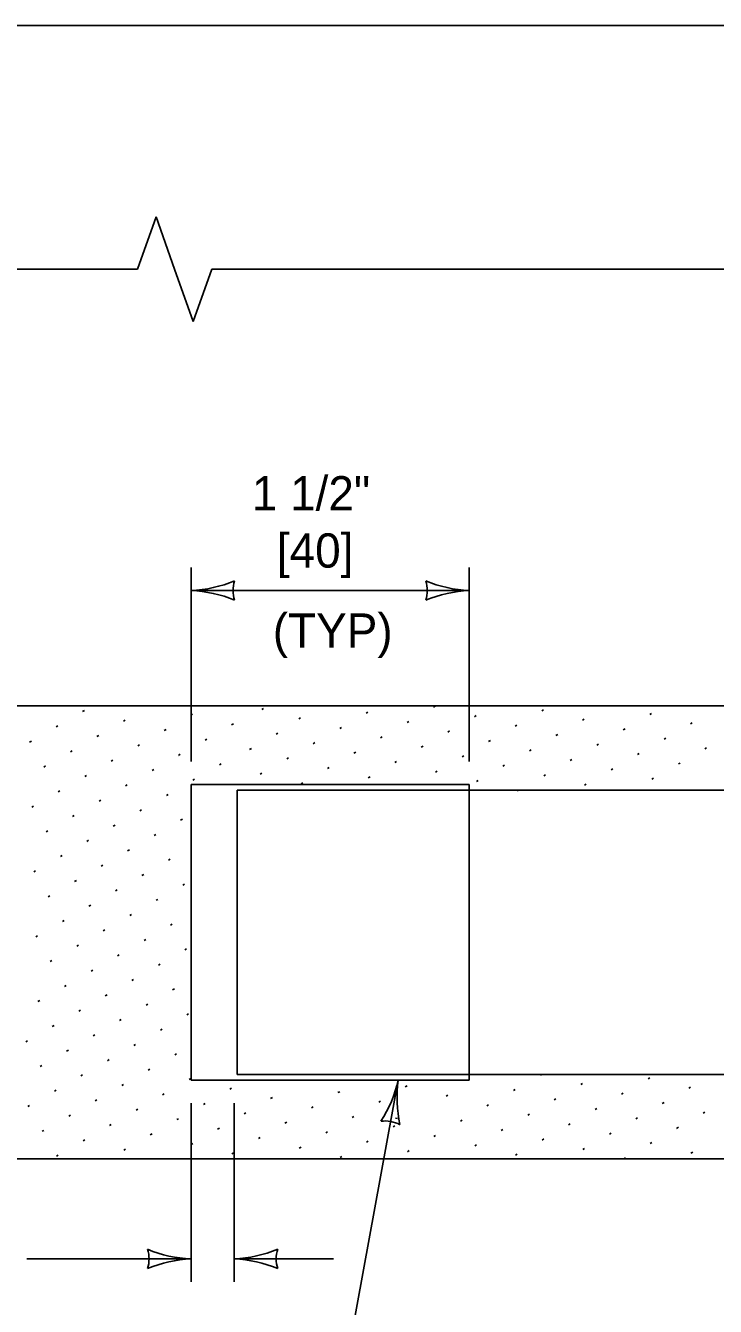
# Model space of a CAD drawing. Extents: x 49991.4 to 50021, y 49987.6 to 50011.4.
# Drawn here: x 50004.674 to 50005.88, y 49996.76 to 49998.999 of the extents above; entities that cross this region are included whole.
import ezdxf

# ---------------------------------------------------------------- set-up
doc = ezdxf.new("R2010")
doc.units = 0
for name, color, linetype in [('Level 1', 7, 'Continuous'), ('Level 2', 7, 'Continuous'), ('Level 3', 7, 'Continuous'), ('Level 4', 7, 'Continuous'), ('Level 6', 7, 'Continuous')]:
    doc.layers.add(name, color=color, linetype=linetype)

msp = doc.modelspace()

# ---------------------------------------------------------------- linework, layer by layer
at = {"layer": 'Level 1'}
for p, q in [((50002.4589, 49997.8102), (50013.6129, 49997.8102)), ((50004.963, 49997.1559), (50004.963, 49997.6726)), ((50005.4493, 49997.6726), (50004.963, 49997.6726)), ((50005.4493, 49997.1559), (50005.4493, 49997.6726)), ((50005.4493, 49997.6626), (50008.0071, 49997.6626)), ((50004.963, 49997.1659), (50004.963, 49997.1659)), ((50008.0071, 49997.1659), (50005.4493, 49997.1659)), ((50005.4493, 49997.1559), (50004.963, 49997.1559)), ((50013.6129, 49997.0183), (50002.4589, 49997.0183))]:
    msp.add_line(p, q, dxfattribs=at)
msp.add_lwpolyline([(49999.3835, 49998.9992), (50016.7501, 49998.9992), (50016.7501, 49987.7988), (49999.3835, 49987.7988)], close=True, dxfattribs=at)
at = {"layer": 'Level 3'}
for p, q in [((50004.963, 49997.7126), (50004.963, 49998.0517)), ((50005.4493, 49997.7126), (50005.4493, 49998.0517)), ((50004.963, 49998.0117), (50005.4493, 49998.0117)), ((50004.7735, 49997.8), (50004.7765, 49997.8018)), ((50004.9625, 49997.7937), (50004.9655, 49997.7954)), ((50005.0868, 49997.8039), (50005.0898, 49997.8056)), ((50005.2692, 49997.7975), (50005.2722, 49997.7993)), ((50005.3868, 49997.8078), (50005.3899, 49997.8095)), ((50005.4582, 49997.7912), (50005.4612, 49997.793)), ((50005.5759, 49997.8014), (50005.5789, 49997.8032)), ((50005.7649, 49997.7951), (50005.7679, 49997.7968)), ((50004.7271, 49997.7733), (50004.7302, 49997.775)), ((50004.8448, 49997.7835), (50004.8478, 49997.7852)), ((50005.0338, 49997.7771), (50005.0369, 49997.7789)), ((50005.1515, 49997.7873), (50005.1545, 49997.7891)), ((50005.2228, 49997.7708), (50005.2259, 49997.7725)), ((50005.3405, 49997.781), (50005.3435, 49997.7827)), ((50005.5295, 49997.7747), (50005.5326, 49997.7764)), ((50005.6472, 49997.7849), (50005.6502, 49997.7866)), ((50005.7185, 49997.7683), (50005.7216, 49997.7701)), ((50005.8362, 49997.7785), (50005.8392, 49997.7803)), ((50004.6808, 49997.7465), (50004.6838, 49997.7483)), ((50004.7985, 49997.7567), (50004.8015, 49997.7585)), ((50004.9161, 49997.7669), (50004.9192, 49997.7687)), ((50004.9875, 49997.7504), (50004.9905, 49997.7521)), ((50005.1118, 49997.7606), (50005.1148, 49997.7623)), ((50005.2942, 49997.7542), (50005.2972, 49997.756)), ((50005.4118, 49997.7644), (50005.4149, 49997.7662)), ((50005.4832, 49997.7479), (50005.4862, 49997.7497)), ((50005.6009, 49997.7581), (50005.6039, 49997.7599)), ((50005.7899, 49997.7518), (50005.7929, 49997.7535)), ((50004.7521, 49997.73), (50004.7552, 49997.7317)), ((50004.8698, 49997.7402), (50004.8728, 49997.7419)), ((50004.9411, 49997.7236), (50004.9442, 49997.7254)), ((50005.0654, 49997.7338), (50005.0685, 49997.7356)), ((50005.1765, 49997.744), (50005.1795, 49997.7458)), ((50005.2478, 49997.7275), (50005.2509, 49997.7292)), ((50005.3655, 49997.7377), (50005.3685, 49997.7394)), ((50005.5545, 49997.7314), (50005.5576, 49997.7331)), ((50005.6722, 49997.7416), (50005.6752, 49997.7433)), ((50005.7435, 49997.725), (50005.7466, 49997.7268)), ((50005.8612, 49997.7352), (50005.8642, 49997.737)), ((50004.7058, 49997.7032), (50004.7088, 49997.705)), ((50004.8235, 49997.7134), (50004.8265, 49997.7152)), ((50005.0125, 49997.7071), (50005.0155, 49997.7088)), ((50005.1302, 49997.7173), (50005.1332, 49997.719)), ((50005.3192, 49997.7109), (50005.3222, 49997.7127)), ((50005.4368, 49997.7211), (50005.4399, 49997.7229)), ((50005.5082, 49997.7046), (50005.5112, 49997.7064)), ((50005.6259, 49997.7148), (50005.6289, 49997.7166)), ((50005.8149, 49997.7085), (50005.8179, 49997.7102)), ((50004.7771, 49997.6867), (50004.7802, 49997.6884)), ((50004.8948, 49997.6969), (50004.8978, 49997.6986)), ((50004.9661, 49997.6803), (50004.9692, 49997.6821)), ((50005.0838, 49997.6905), (50005.0869, 49997.6923)), ((50005.2015, 49997.7007), (50005.2045, 49997.7025)), ((50005.2728, 49997.6842), (50005.2759, 49997.6859)), ((50005.3905, 49997.6944), (50005.3935, 49997.6961)), ((50005.5795, 49997.6881), (50005.5826, 49997.6898)), ((50005.6972, 49997.6983), (50005.7002, 49997.7)), ((50005.7685, 49997.6817), (50005.7716, 49997.6835)), ((50004.7308, 49997.6599), (50004.7338, 49997.6617)), ((50004.8485, 49997.6701), (50004.8515, 49997.6719)), ((50005.1552, 49997.674), (50005.1582, 49997.6757)), ((50005.4618, 49997.6778), (50005.4649, 49997.6796)), ((50005.5332, 49997.6613), (50005.5362, 49997.663)), ((50005.6509, 49997.6715), (50005.6539, 49997.6733)), ((50004.8021, 49997.6434), (50004.8052, 49997.6451)), ((50004.9198, 49997.6536), (50004.9228, 49997.6553)), ((50004.6845, 49997.6332), (50004.6875, 49997.6349)), ((50004.7558, 49997.6166), (50004.7588, 49997.6184)), ((50004.8735, 49997.6268), (50004.8765, 49997.6286)), ((50004.7095, 49997.5899), (50004.7125, 49997.5916)), ((50004.8271, 49997.6001), (50004.8302, 49997.6018)), ((50004.9448, 49997.6103), (50004.9478, 49997.612)), ((50004.7808, 49997.5733), (50004.7838, 49997.5751)), ((50004.8985, 49997.5835), (50004.9015, 49997.5853)), ((50004.7345, 49997.5466), (50004.7375, 49997.5483)), ((50004.8521, 49997.5568), (50004.8552, 49997.5585)), ((50004.8058, 49997.53), (50004.8088, 49997.5318)), ((50004.9235, 49997.5402), (50004.9265, 49997.542)), ((50004.6881, 49997.5198), (50004.6911, 49997.5216)), ((50004.7595, 49997.5033), (50004.7625, 49997.505)), ((50004.8771, 49997.5135), (50004.8802, 49997.5152)), ((50004.8308, 49997.4867), (50004.8338, 49997.4885)), ((50004.9485, 49997.4969), (50004.9515, 49997.4987)), ((50004.7131, 49997.4765), (50004.7161, 49997.4783)), ((50004.7845, 49997.46), (50004.7875, 49997.4617)), ((50004.9021, 49997.4702), (50004.9052, 49997.4719)), ((50004.7381, 49997.4332), (50004.7411, 49997.435)), ((50004.8558, 49997.4434), (50004.8588, 49997.4452)), ((50004.8095, 49997.4167), (50004.8125, 49997.4184)), ((50004.9271, 49997.4269), (50004.9302, 49997.4286)), ((50004.6918, 49997.4064), (50004.6948, 49997.4082)), ((50004.7631, 49997.3899), (50004.7661, 49997.3917)), ((50004.8808, 49997.4001), (50004.8838, 49997.4019)), ((50004.8345, 49997.3734), (50004.8375, 49997.3751)), ((50004.9521, 49997.3836), (50004.9552, 49997.3853)), ((50004.7168, 49997.3631), (50004.7198, 49997.3649)), ((50004.7881, 49997.3466), (50004.7911, 49997.3483)), ((50004.9058, 49997.3568), (50004.9088, 49997.3586)), ((50004.8595, 49997.3301), (50004.8625, 49997.3318)), ((50004.7418, 49997.3198), (50004.7448, 49997.3216)), ((50004.8131, 49997.3033), (50004.8161, 49997.305)), ((50004.9308, 49997.3135), (50004.9338, 49997.3153)), ((50004.6954, 49997.2931), (50004.6985, 49997.2948)), ((50004.7668, 49997.2765), (50004.7698, 49997.2783)), ((50004.8845, 49997.2868), (50004.8875, 49997.2885)), ((50004.8381, 49997.26), (50004.8411, 49997.2617)), ((50004.9558, 49997.2702), (50004.9588, 49997.272)), ((50004.7204, 49997.2498), (50004.7235, 49997.2515)), ((50004.7918, 49997.2332), (50004.7948, 49997.235)), ((50004.9095, 49997.2434), (50004.9125, 49997.2452)), ((50004.6741, 49997.223), (50004.6771, 49997.2248)), ((50004.8631, 49997.2167), (50004.8661, 49997.2184)), ((50004.7454, 49997.2065), (50004.7485, 49997.2082)), ((50004.8168, 49997.1899), (50004.8198, 49997.1917)), ((50004.9345, 49997.2001), (50004.9375, 49997.2019)), ((50004.6991, 49997.1797), (50004.7021, 49997.1815)), ((50004.8881, 49997.1734), (50004.8911, 49997.1751)), ((50005.5737, 49997.1646), (50005.5759, 49997.1659)), ((50004.7704, 49997.1632), (50004.7735, 49997.1649)), ((50004.8418, 49997.1466), (50004.8448, 49997.1484)), ((50004.9595, 49997.1568), (50004.9625, 49997.1586)), ((50005.2052, 49996.4992), (50005.3252, 49997.1559)), ((50005.3375, 49997.1442), (50005.3405, 49997.1459)), ((50005.6442, 49997.148), (50005.6472, 49997.1498)), ((50005.7618, 49997.1582), (50005.7649, 49997.16)), ((50005.8332, 49997.1417), (50005.8362, 49997.1434)), ((50004.7241, 49997.1364), (50004.7271, 49997.1382)), ((50004.7954, 49997.1199), (50004.7985, 49997.1216)), ((50004.9131, 49997.1301), (50004.9161, 49997.1318)), ((50005.0308, 49997.1403), (50005.0338, 49997.142)), ((50005.1021, 49997.1238), (50005.1052, 49997.1255)), ((50005.2198, 49997.134), (50005.2228, 49997.1357)), ((50005.4088, 49997.1276), (50005.4118, 49997.1294)), ((50005.5265, 49997.1378), (50005.5295, 49997.1396)), ((50005.5978, 49997.1213), (50005.6009, 49997.123)), ((50005.7155, 49997.1315), (50005.7185, 49997.1332)), ((50004.6778, 49997.1097), (50004.6808, 49997.1114)), ((50004.8668, 49997.1033), (50004.8698, 49997.1051)), ((50004.963, 49996.8034), (50004.963, 49997.1159)), ((50004.9845, 49997.1135), (50004.9875, 49997.1153)), ((50005.0384, 49996.8034), (50005.0384, 49997.1159)), ((50005.0558, 49997.097), (50005.0588, 49997.0987)), ((50005.1735, 49997.1072), (50005.1765, 49997.109)), ((50005.2911, 49997.1174), (50005.2942, 49997.1192)), ((50005.4802, 49997.1111), (50005.4832, 49997.1128)), ((50005.6692, 49997.1047), (50005.6722, 49997.1065)), ((50005.7868, 49997.1149), (50005.7899, 49997.1167)), ((50005.8582, 49997.0984), (50005.8612, 49997.1001)), ((50004.7491, 49997.0931), (50004.7521, 49997.0949)), ((50004.8204, 49997.0766), (50004.8235, 49997.0783)), ((50004.9381, 49997.0868), (50004.9411, 49997.0885)), ((50005.1271, 49997.0804), (50005.1302, 49997.0822)), ((50005.2448, 49997.0907), (50005.2478, 49997.0924)), ((50005.3202, 49997.0896), (50005.3237, 49997.0891)), ((50005.4338, 49997.0843), (50005.4368, 49997.0861)), ((50005.5515, 49997.0945), (50005.5545, 49997.0963)), ((50005.6228, 49997.078), (50005.6259, 49997.0797)), ((50005.7405, 49997.0882), (50005.7435, 49997.0899)), ((50004.7028, 49997.0664), (50004.7058, 49997.0681)), ((50004.8918, 49997.06), (50004.8948, 49997.0618)), ((50005.0095, 49997.0702), (50005.0125, 49997.072)), ((50005.0808, 49997.0537), (50005.0838, 49997.0554)), ((50005.1985, 49997.0639), (50005.2015, 49997.0657)), ((50005.3161, 49997.0741), (50005.3192, 49997.0759)), ((50005.3875, 49997.0576), (50005.3905, 49997.0593)), ((50005.5052, 49997.0678), (50005.5082, 49997.0695)), ((50005.6942, 49997.0614), (50005.6972, 49997.0632)), ((50005.8118, 49997.0716), (50005.8149, 49997.0734)), ((50004.7741, 49997.0498), (50004.7771, 49997.0516)), ((50004.8454, 49997.0333), (50004.8485, 49997.035)), ((50004.9631, 49997.0435), (50004.9661, 49997.0452)), ((50005.1521, 49997.0371), (50005.1552, 49997.0389)), ((50005.2698, 49997.0474), (50005.2728, 49997.0491)), ((50005.3411, 49997.0308), (50005.3442, 49997.0326)), ((50005.4588, 49997.041), (50005.4618, 49997.0428)), ((50005.5765, 49997.0512), (50005.5795, 49997.053)), ((50005.6478, 49997.0347), (50005.6509, 49997.0364)), ((50005.7655, 49997.0449), (50005.7685, 49997.0466)), ((50004.7278, 49997.0231), (50004.7308, 49997.0248)), ((50004.9194, 49997.0183), (50004.9198, 49997.0185)), ((50005.0345, 49997.0269), (50005.0375, 49997.0287)), ((50005.2235, 49997.0206), (50005.2265, 49997.0224)), ((50005.5302, 49997.0245), (50005.5332, 49997.0262)), ((50005.7194, 49997.0183), (50005.7222, 49997.0199)), ((50005.8368, 49997.0283), (50005.8399, 49997.0301)), ((50004.6757, 49996.8434), (50004.963, 49996.8434)), ((50005.0384, 49996.8434), (50005.2118, 49996.8434))]:
    msp.add_line(p, q, dxfattribs=at)
for centre, radius, start, end in [((50004.9515, 49998.2444), 0.233, 272.8273, 292.0772), ((50005.0912, 49998.0117), 0.0548, 162.1388, 197.8612), ((50005.4584, 49998.2339), 0.2223, 247.456, 267.6395), ((50005.321, 49998.0117), 0.0548, 342.1388, 17.8612), ((50004.9539, 49997.7896), 0.2223, 67.456, 87.6395), ((50005.4608, 49997.779), 0.233, 92.8273, 112.0772), ((50005.1083, 49997.2048), 0.2223, 327.1033, 347.2868), ((50005.5562, 49997.1254), 0.233, 172.4746, 191.7244), ((50005.3022, 49997.0297), 0.0548, 61.7861, 97.5084), ((50004.9722, 49997.0655), 0.2223, 247.456, 267.6395), ((50004.8348, 49996.8434), 0.0548, 342.1388, 17.8612), ((50005.0269, 49997.0761), 0.233, 272.8273, 292.0772), ((50005.1666, 49996.8434), 0.0548, 162.1388, 197.8612), ((50004.9745, 49996.6107), 0.233, 92.8273, 112.0772), ((50005.0292, 49996.6213), 0.2223, 67.456, 87.6395)]:
    msp.add_arc(centre, radius, start, end, dxfattribs=at)
at = {"layer": 'Level 4'}
for p, q in [((50005.4493, 49997.6626), (50005.0436, 49997.6626)), ((50005.0436, 49997.6626), (50005.0436, 49997.1659)), ((50005.0436, 49997.1659), (50005.4493, 49997.1659))]:
    msp.add_line(p, q, dxfattribs=at)
at = {"layer": 'Level 6'}
for p, q in [((50004.8695, 49998.5733), (50004.9019, 49998.6647)), ((50004.9343, 49998.5733), (50004.9019, 49998.6647)), ((50004.8695, 49998.5733), (50001.9365, 49998.5733)), ((50004.9667, 49998.4819), (50004.9343, 49998.5733)), ((50004.9667, 49998.4819), (50004.9991, 49998.5733)), ((50011.4626, 49998.5733), (50004.9991, 49998.5733))]:
    msp.add_line(p, q, dxfattribs=at)

# ---------------------------------------------------------------- texts
at = {"layer": 'Level 2'}
for s, p in [('1 1/2"', (50005.0692, 49998.1517)), ('[40]', (50005.113, 49998.0517)), ('(TYP)', (50005.1059, 49997.9117))]:
    msp.add_text(s, height=0.06, dxfattribs=at).set_placement(p)

doc.saveas('drawing.dxf')
